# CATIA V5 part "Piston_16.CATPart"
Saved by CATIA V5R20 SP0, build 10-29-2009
Part number: Piston_16
Bounding box of the stored display mesh (mm): x -15 to 15, y 0 to 186.179, z -15 to 15
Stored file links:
  C:\Users\Thinkmotion2\Desktop\Pack 2\CFAO_2010\abaussand\CFAO_abaussand_Catia_V5R20\Piston_16.CATPart
  C:\Users\Alex\IFMA\2A\CFAO\pompe\pompe.CATProduct
  C:\Users\Thinkmotion2\Desktop\Pack 2\CFAO_2010\abaussand\CFAO_abaussand_Catia_V5R20\corps_12.CATPart
  C:\Users\Thinkmotion2\Desktop\Pack 2\CFAO_2010\abaussand\CFAO_abaussand_Catia_V5R20\Plan_incline_18.CATPart
  C:\Users\Thinkmotion2\Desktop\Pack 2\CFAO_2010\abaussand\CFAO_abaussand_Catia_V5R20\abaussand_2.CATProduct
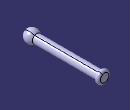
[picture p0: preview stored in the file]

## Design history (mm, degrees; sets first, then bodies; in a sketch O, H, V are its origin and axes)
Parameters
  longueur_piston = 150 mm
External parameters (linked from other documents)
  `External.Diamètre_piston_16` = 30 mm
Body1 (main body)
  Sketch1 on yz-plane, origin (0, 0, 0), H (0, 1, 0), V (0, 0, 1)
    arc A1 centre (15, 0) radius 15 from (0, 0) to (26.1803, 10) cw
    point P1 (15, 0)
    point P2 (26.1803, 10)
    line L1 (26.1803, 10) -> (176.1803, 10)
    line L2 (176.1803, 10) -> (176.1803, 10)
    line L3 (186.1788, 9.8752) -> (186.1788, 0)
    point P6 (186.1788, 0)
    line L4 (186.1788, 0) -> (0, 0)
    arc A2 centre (181.1803, 10) radius 5 from (176.1803, 10) to (186.1788, 9.8752) cw
    point P7 (181.1803, 10)
    radius A1 = 15 {= `External.Diamètre_piston_16`  /  2}
    distance P2 H = 10
    length L1 = 150 {= longueur_piston}
    radius A2 = 5
    distance P7 L4 = 10
    horizontal: L1 H, L4 H
    vertical: L2 V, L3 V
    coincidence: P6 H, P1 L4
  Shaft1: profile Sketch1, axis Sketch1.L4, angle 360
  Sketch2 on xy-plane, origin (0, 0, 0), H (1, 0, 0), V (0, 1, 0)
    point P1 (0, 15)
    point P2 (0, 181.1788)
    reference projected line E1 (-9.8752, 186.1788) -> (9.8752, 186.1788) from edge [face of Shaft1 from Sketch1.A2 | face of Shaft1 from Sketch1.L3]
    distance P1 H = 15 {= `External.Diamètre_piston_16` /2}
    distance P2 E1 = 5
    distance P2 V = 0
    coincidence: P1 V
  Point1: type Center, Curve edge [face of Shaft1 from Sketch1.A2 | face of Shaft1 from Sketch1.L3]
  Point2: type Center, Curve edge [face of Shaft1 from Sketch1.L1 | face of Shaft1 from Sketch1.A2]
  Point3: type Between, FirstPoint Point1, SecondPoint Point2, Ratio 0.5
  Sketch3 on yz-plane, origin (0, 0, 0), H (0, 1, 0), V (0, 0, 1)
    arc A1 centre (181.1796, 10) radius 5 from (186.1796, 10) to (176.1796, 10) ccw
    point P1 (181.1796, 10)
    axis line L1 (176.1796, 10) -> (186.1796, 10)
    reference projected line E1 through (0, 0) direction (1, 0) from axis of face of Shaft1 from Sketch1.L1
    reference projected line E2 (176.1803, 10) -> (176.1803, -10) from edge [face of Shaft1 from Sketch1.L1 | face of Shaft1 from Sketch1.A2]
    reference projected line E3 (186.1788, 9.8752) -> (186.1788, -9.8752) from edge [face of Shaft1 from Sketch1.A2 | face of Shaft1 from Sketch1.L3]
    radius A1 = 5
    distance L1 E1 = 10
    horizontal: L1 H
    coincidence: P1 L1
    equidistance: E2 E3 P1
  Point4: type Center, Curve face of Shaft1 from Sketch1.A1
  Line1: type PtDir, RefPoint Point4, Direction yz-plane, Start -20, End 20
  Sketch4 on yz-plane, origin (0, 0, 0), H (0, 1, 0), V (0, 0, 1)
    circle A1 centre (15, 0) radius 3
    point P1 (15, 0)
    reference projected point E1 (15, 0) from edge
    radius A1 = 3
    coincidence: P1 H, P1 E1
  Pocket1: profile Sketch4, direction (-1, 0, 0), length 5, opposite side length 5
